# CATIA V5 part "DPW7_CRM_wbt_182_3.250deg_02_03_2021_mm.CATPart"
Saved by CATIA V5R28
Part number: DPW7_CRM_wbt_182_3.250deg_02_03_2021
Bounding box of the stored display mesh (mm): x 2349.5 to 66711.891, y 0 to 29459.83, z 2310.119 to 8715.756
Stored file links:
  Z:\Scratch\04_CAD_Allgemein\Flight2Jig\Output\DPW-7\CATPart\DPW7_CRM_wbt_182_3.250deg_02_03_2021.CATPart
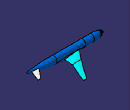
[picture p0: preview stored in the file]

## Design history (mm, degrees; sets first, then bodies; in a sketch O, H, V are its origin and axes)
Set1
  DatumSurface1 "Clean_Wing"
  DatumSurface2 "Fuselage"
  DatumSurface3 "HTP"
  DatumSurface4 "Symmetry"
  DatumSurface5 "Farfield"
Body1 (main body)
